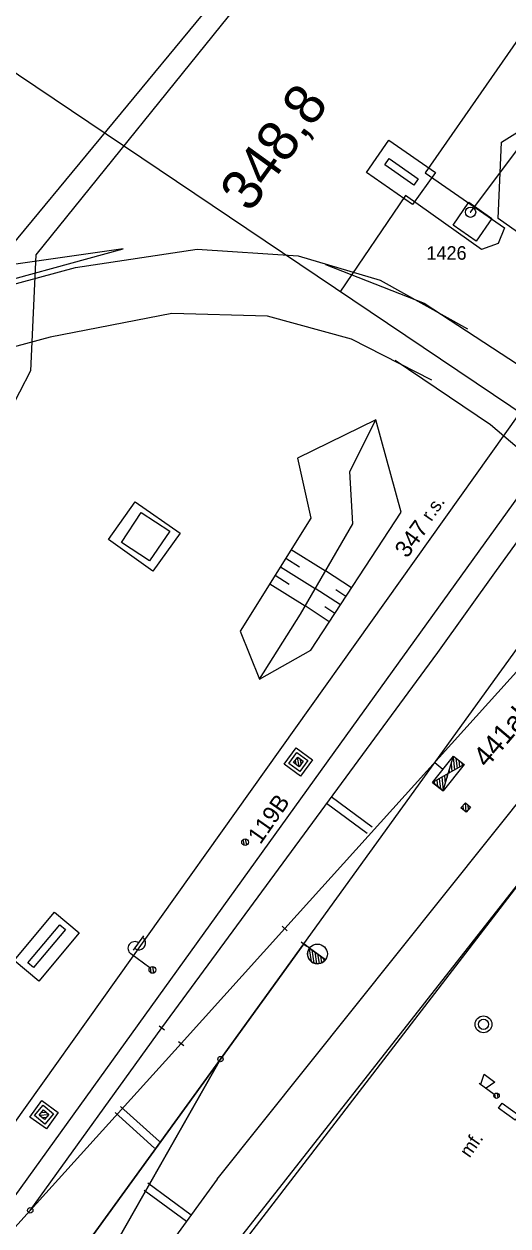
# Model space of a CAD drawing. Extents: x -469926 to -462499, y -1098642 to -1092733.
# Drawn here: x -465755.3 to -465719.5, y -1095836.3 to -1095747.3 of the extents above; entities that cross this region are included whole.
import ezdxf

# ---------------------------------------------------------------- set-up
doc = ezdxf.new("R2010")
doc.units = 0
for name, color, linetype in [('Vrstva 1', 7, 'Continuous'), ('Vrstva 11', 7, 'Continuous'), ('Vrstva 12', 7, 'Continuous'), ('Vrstva 13', 7, 'Continuous'), ('Vrstva 16', 7, 'Continuous'), ('Vrstva 2', 7, 'Continuous'), ('Vrstva 46', 7, 'Continuous'), ('Vrstva 48', 7, 'Continuous'), ('Vrstva 50', 7, 'Continuous'), ('Vrstva 51', 7, 'Continuous'), ('Vrstva 55', 7, 'Continuous'), ('Vrstva 58', 7, 'Continuous'), ('Vrstva 62', 7, 'Continuous'), ('Vrstva 7', 7, 'Continuous')]:
    doc.layers.add(name, color=color, linetype=linetype)

msp = doc.modelspace()

# ---------------------------------------------------------------- linework, layer by layer
at = {"layer": 'Vrstva 1'}
for p, q in [((-465788.8, -1095874.65), (-465635.97, -1095660.09)), ((-465720.35, -1095787.76), (-465712.45, -1095776.88)), ((-465734.607, -1095815.42), (-465712.071, -1095784.2)), ((-465736.023, -1095814.275), (-465710.284, -1095785.74)), ((-465741.022, -1095832.841), (-465709.466, -1095793.302)), ((-465754.17, -1095857.1), (-465718.76, -1095811.1)), ((-465750.523, -1095837.402), (-465740.776, -1095823.941))]:
    msp.add_line(p, q, dxfattribs=at)
for points in [[(-465745.127, -1095821.621), (-465724.675, -1095793.843), (-465720.35, -1095787.76)], [(-465736.023, -1095814.275), (-465743.694, -1095822.788)], [(-465734.607, -1095815.42), (-465740.776, -1095823.941), (-465750.523, -1095837.402)], [(-465775.781, -1095858.01), (-465766.01, -1095847.458), (-465754.867, -1095835.14), (-465745.127, -1095821.621)], [(-465766.01, -1095847.458), (-465754.867, -1095835.14), (-465743.694, -1095822.788)], [(-465754.867, -1095835.14), (-465743.694, -1095822.788)], [(-465741.022, -1095832.841), (-465753.551, -1095850.09), (-465764.044, -1095864.57)]]:
    msp.add_lwpolyline(points, dxfattribs=at)
at = {"layer": 'Vrstva 12'}
for p, q in [((-465735.172, -1095802.135), (-465735.221, -1095801.808)), ((-465734.959, -1095802.293), (-465735.063, -1095801.595)), ((-465734.801, -1095802.082), (-465734.85, -1095801.751)), ((-465722.598, -1095805.672), (-465722.64, -1095804.968)), ((-465722.796, -1095805.496), (-465722.816, -1095805.166)), ((-465722.422, -1095805.476), (-465722.441, -1095805.142)), ((-465754.192, -1095828.09), (-465753.489, -1095828.032)), ((-465754.021, -1095827.887), (-465753.691, -1095827.86)), ((-465753.993, -1095828.261), (-465753.659, -1095828.234))]:
    msp.add_line(p, q, dxfattribs=at)
for points in [[(-465735.169, -1095800.895), (-465733.961, -1095801.785), (-465734.851, -1095802.993), (-465736.059, -1095802.103)], [(-465735.71, -1095802.047), (-465735.113, -1095801.244), (-465734.31, -1095801.841), (-465734.907, -1095802.644)], [(-465735.36, -1095801.996), (-465735.062, -1095801.594), (-465734.66, -1095801.892), (-465734.958, -1095802.294)], [(-465722.971, -1095805.341), (-465722.639, -1095804.967), (-465722.265, -1095805.299), (-465722.597, -1095805.673)], [(-465754.011, -1095827.015), (-465752.794, -1095827.892), (-465753.671, -1095829.109), (-465754.888, -1095828.232)], [(-465753.898, -1095827.356), (-465753.135, -1095828.005), (-465753.784, -1095828.768), (-465754.547, -1095828.119)], [(-465753.87, -1095827.709), (-465753.488, -1095828.033), (-465753.812, -1095828.414), (-465754.193, -1095828.091)]]:
    msp.add_lwpolyline(points, close=True, dxfattribs=at)
for points in [[(-465735.36, -1095801.996), (-465735.062, -1095801.594), (-465734.66, -1095801.892), (-465734.958, -1095802.294), (-465735.36, -1095801.996)], [(-465722.971, -1095805.341), (-465722.639, -1095804.967), (-465722.265, -1095805.299), (-465722.597, -1095805.673), (-465722.971, -1095805.341)], [(-465753.87, -1095827.709), (-465753.488, -1095828.033), (-465753.812, -1095828.414), (-465754.193, -1095828.091), (-465753.87, -1095827.709)]]:
    msp.add_lwpolyline(points, dxfattribs=at)
at = {"layer": 'Vrstva 13'}
for p, q in [((-465733.01, -1095765.12), (-465725.7, -1095767.97)), ((-465725.7, -1095767.97), (-465717.46, -1095773.38)), ((-465727.85, -1095772.21), (-465720.79, -1095776.97)), ((-465720.79, -1095776.97), (-465716.442, -1095780.676))]:
    msp.add_line(p, q, dxfattribs=at)
for points in [[(-465838.428, -1095771.566), (-465834.57, -1095778.174), (-465829.935, -1095781.442), (-465824.938, -1095782.605), (-465818.606, -1095782.506), (-465808.495, -1095780.589), (-465777.214, -1095772.3), (-465751.524, -1095765.336), (-465742.5, -1095763.978), (-465735.021, -1095764.484), (-465728.964, -1095766.278), (-465722.487, -1095769.872)], [(-465725.124, -1095773.69), (-465731.083, -1095770.643), (-465737.306, -1095768.943), (-465744.388, -1095768.752), (-465753.392, -1095770.491), (-465774.436, -1095776.17), (-465804.42, -1095784.289), (-465857.81, -1095799.241), (-465876.937, -1095806.252), (-465888.375, -1095812.085), (-465898.457, -1095818.323), (-465902.347, -1095822), (-465903.923, -1095826.471), (-465903.648, -1095830.838), (-465902.613, -1095834.901), (-465899.413, -1095840.431), (-465874.372, -1095879.591), (-465865.495, -1095894.209)]]:
    msp.add_lwpolyline(points, dxfattribs=at)
at = {"layer": 'Vrstva 16'}
for p, q in [((-465722.26, -1095761.25), (-465583.59, -1095575.87)), ((-465722.285, -1095761.25), (-465722.235, -1095761.25))]:
    msp.add_line(p, q, dxfattribs=at)
msp.add_circle((-465722.26, -1095761.25), 0.378, dxfattribs=at)
at = {"layer": 'Vrstva 2'}
for p, q in [((-465724.306, -1095802.495), (-465724.895, -1095802.021)), ((-465723.699, -1095802.093), (-465723.637, -1095802.647)), ((-465723.552, -1095801.606), (-465723.447, -1095802.539)), ((-465723.345, -1095801.658), (-465723.258, -1095802.432)), ((-465723.124, -1095801.834), (-465723.069, -1095802.324)), ((-465722.903, -1095802.01), (-465722.88, -1095802.217)), ((-465724.77, -1095803.292), (-465724.718, -1095803.761)), ((-465724.581, -1095803.184), (-465724.496, -1095803.938)), ((-465724.392, -1095803.076), (-465724.284, -1095804.035)), ((-465724.203, -1095802.969), (-465724.137, -1095803.549)), ((-465724.014, -1095802.861), (-465723.991, -1095803.063)), ((-465723.845, -1095802.579), (-465723.826, -1095802.754)), ((-465724.96, -1095803.399), (-465724.939, -1095803.585))]:
    msp.add_line(p, q, dxfattribs=at)
msp.add_lwpolyline([(-465722.743, -1095802.139), (-465724.302, -1095804.093), (-465725.084, -1095803.47), (-465723.525, -1095801.515)], close=True, dxfattribs=at)
for points in [[(-465722.743, -1095802.139), (-465723.913, -1095802.804), (-465723.525, -1095801.515), (-465722.743, -1095802.139)], [(-465724.302, -1095804.093), (-465723.913, -1095802.804), (-465725.084, -1095803.47), (-465724.302, -1095804.093)]]:
    msp.add_lwpolyline(points, dxfattribs=at)
at = {"layer": 'Vrstva 46'}
msp.add_lwpolyline([(-465739.37, -1095837.25), (-465718.79, -1095811.03), (-465716.12, -1095812.96), (-465704.25, -1095819.84)], dxfattribs=at)
at = {"layer": 'Vrstva 48'}
for points in [[(-465735.544, -1095786.219), (-465733, -1095787.804)], [(-465735.941, -1095786.856), (-465734.916, -1095787.494)], [(-465736.734, -1095788.129), (-465735.694, -1095788.777)], [(-465736.337, -1095787.492), (-465733.756, -1095789.101)], [(-465731.077, -1095789.063), (-465732.999, -1095787.802)], [(-465737.131, -1095788.765), (-465734.513, -1095790.397)], [(-465731.899, -1095790.317), (-465733.756, -1095789.099)], [(-465731.488, -1095789.69), (-465732.244, -1095789.194)], [(-465732.722, -1095791.571), (-465734.513, -1095790.397)], [(-465732.31, -1095790.944), (-465733.04, -1095790.466)]]:
    msp.add_lwpolyline(points, dxfattribs=at)
at = {"layer": 'Vrstva 50'}
msp.add_line((-465757.57, -1095765.332), (-465684.425, -1095676.798), dxfattribs=at)
at = {"layer": 'Vrstva 51'}
for p, q in [((-465684.073, -1095677.119), (-465754.445, -1095764.415)), ((-465754.445, -1095764.415), (-465754.852, -1095772.991)), ((-465754.852, -1095772.991), (-465783.762, -1095828.944))]:
    msp.add_line(p, q, dxfattribs=at)
at = {"layer": 'Vrstva 55'}
for p, q in [((-465722.26, -1095761.25), (-465583.59, -1095575.87)), ((-465722.285, -1095761.25), (-465722.235, -1095761.25)), ((-465731.045, -1095806.019), (-465731.045, -1095806.019)), ((-465739.009, -1095808.128), (-465739.099, -1095807.68)), ((-465738.824, -1095808.094), (-465738.916, -1095807.64)), ((-465747.216, -1095815.867), (-465746.442, -1095814.822)), ((-465736.213, -1095814.112), (-465735.833, -1095814.438)), ((-465736.023, -1095814.275), (-465736.023, -1095814.275)), ((-465740.776, -1095823.941), (-465734.607, -1095815.42)), ((-465734.804, -1095815.265), (-465734.41, -1095815.575)), ((-465734.607, -1095815.42), (-465734.607, -1095815.42)), ((-465734.19, -1095815.722), (-465734.607, -1095815.42)), ((-465734.191, -1095815.723), (-465734.19, -1095815.722)), ((-465733.008, -1095816.585), (-465734.191, -1095815.723)), ((-465734.19, -1095815.722), (-465733.008, -1095816.585)), ((-465746.018, -1095817.19), (-465747.424, -1095816.148)), ((-465734.22, -1095815.77), (-465734.074, -1095816.709)), ((-465734.019, -1095815.848), (-465733.864, -1095816.835)), ((-465733.804, -1095816.004), (-465733.667, -1095816.881)), ((-465733.591, -1095816.161), (-465733.479, -1095816.874)), ((-465733.376, -1095816.317), (-465733.298, -1095816.819)), ((-465733.162, -1095816.473), (-465733.125, -1095816.709)), ((-465745.901, -1095817.575), (-465745.966, -1095817.139)), ((-465745.712, -1095817.565), (-465745.783, -1095817.091)), ((-465754.867, -1095835.14), (-465745.127, -1095821.621)), ((-465745.329, -1095821.473), (-465744.925, -1095821.769)), ((-465745.127, -1095821.621), (-465745.127, -1095821.621)), ((-465743.896, -1095822.639), (-465743.492, -1095822.937)), ((-465743.694, -1095822.788), (-465743.694, -1095822.788)), ((-465740.776, -1095823.941), (-465748.993, -1095838.414)), ((-465721.51, -1095825.801), (-465721.264, -1095825.05)), ((-465721.264, -1095825.05), (-465720.461, -1095825.647)), ((-465721.631, -1095825.712), (-465720.507, -1095826.544)), ((-465720.461, -1095825.647), (-465721.109, -1095826.1)), ((-465720.41, -1095826.842), (-465720.461, -1095826.497)), ((-465720.212, -1095826.809), (-465720.262, -1095826.471)), ((-465746.882, -1095829.036), (-465746.882, -1095829.036)), ((-465744.497, -1095834.692), (-465744.497, -1095834.692))]:
    msp.add_line(p, q, dxfattribs=at)
for points in [[(-465609.888, -1095625.282), (-465638.963, -1095671.505), (-465681.941, -1095731.193), (-465731.933, -1095800.622), (-465757.477, -1095836.099), (-465808.227, -1095887.932), (-465849.014, -1095921.297)], [(-465777.86, -1095736.176), (-465714.07, -1095779.117)], [(-465707.358, -1095756.532), (-465711.944, -1095759.891), (-465717.519, -1095763.613), (-465720.23, -1095761.71), (-465719.982, -1095756.053), (-465713.877, -1095752.269)], [(-465729.964, -1095758.307), (-465728.301, -1095755.91), (-465724.854, -1095758.302), (-465726.562, -1095760.668), (-465729.964, -1095758.307)], [(-465728.612, -1095757.735), (-465728.297, -1095757.284), (-465726.144, -1095758.788), (-465726.459, -1095759.239), (-465728.612, -1095757.735)], [(-465723.562, -1095762.202), (-465722.382, -1095760.501), (-465720.683, -1095761.703), (-465721.853, -1095763.388), (-465723.562, -1095762.202)], [(-465838.428, -1095771.566), (-465834.57, -1095778.174), (-465829.935, -1095781.442), (-465824.938, -1095782.605), (-465818.606, -1095782.506), (-465808.495, -1095780.589), (-465777.214, -1095772.3), (-465751.524, -1095765.336), (-465742.5, -1095763.978), (-465735.021, -1095764.484), (-465728.964, -1095766.278), (-465722.487, -1095769.872)], [(-465785.648, -1095773.98), (-465759.87, -1095767.225), (-465747.992, -1095763.955), (-465767.148, -1095766.706), (-465788.561, -1095771.396)], [(-465737.882, -1095795.826), (-465734.099, -1095793.672), (-465727.404, -1095783.462), (-465729.286, -1095776.626), (-465735.077, -1095779.458), (-465734.095, -1095783.893), (-465739.313, -1095792.266), (-465737.882, -1095795.826)], [(-465737.882, -1095795.826), (-465734.865, -1095791), (-465730.967, -1095784.318), (-465731.189, -1095780.453), (-465729.286, -1095776.626)], [(-465749.069, -1095785.489), (-465747.084, -1095782.679), (-465743.773, -1095785.017), (-465745.777, -1095787.813), (-465749.069, -1095785.489)], [(-465748.108, -1095785.697), (-465746.641, -1095783.466), (-465744.527, -1095784.856), (-465746.034, -1095787.059), (-465748.108, -1095785.697)], [(-465732.937, -1095804.991), (-465729.923, -1095807.216)], [(-465732.58, -1095804.509), (-465729.537, -1095806.742)], [(-465756.048, -1095816.638), (-465753.075, -1095813.072), (-465751.241, -1095814.595), (-465754.217, -1095818.165), (-465756.048, -1095816.638)], [(-465755.035, -1095816.809), (-465752.673, -1095814.002), (-465752.252, -1095814.356), (-465754.614, -1095817.163), (-465755.035, -1095816.809)], [(-465748.993, -1095838.414), (-465740.776, -1095823.941)], [(-465720.198, -1095827.585), (-465719.932, -1095827.21), (-465718.698, -1095828.092), (-465718.956, -1095828.469), (-465720.198, -1095827.585)], [(-465745.661, -1095830.54), (-465748.576, -1095827.907)], [(-465745.305, -1095830.051), (-465748.173, -1095827.462)], [(-465746.147, -1095833.111), (-465742.944, -1095835.459)], [(-465746.438, -1095833.637), (-465743.299, -1095835.943)]]:
    msp.add_lwpolyline(points, dxfattribs=at)
for centre, radius in [((-465722.26, -1095761.25), 0.378), ((-465738.958, -1095807.885), 0.25), ((-465733.597, -1095816.157), 0.731), ((-465745.817, -1095817.339), 0.25), ((-465745.817, -1095817.339), 0.25), ((-465721.301, -1095821.368), 0.623), ((-465721.301, -1095821.368), 0.376), ((-465740.776, -1095823.941), 0.2), ((-465720.34, -1095826.655), 0.201), ((-465720.34, -1095826.655), 0.2), ((-465754.867, -1095835.14), 0.2)]:
    msp.add_circle(centre, radius, dxfattribs=at)
for centre, radius, start, end in [((-465747.126, -1095815.746), 0.5, 53.45662, 233.45662), ((-465746.823, -1095815.348), 0.5, 232.75405, 54.15919), ((-465733.6, -1095816.154), 0.732, 143.90059, 323.86144)]:
    msp.add_arc(centre, radius, start, end, dxfattribs=at)
at = {"layer": 'Vrstva 58'}
for points in [[(-465691.234, -1095708.918), (-465725.631, -1095758.328)], [(-465725.631, -1095758.328), (-465719.746, -1095762.401), (-465720.206, -1095763.559), (-465721.447, -1095764.009), (-465727.067, -1095760.015)], [(-465727.067, -1095760.015), (-465731.936, -1095767.169)]]:
    msp.add_lwpolyline(points, dxfattribs=at)
at = {"layer": 'Vrstva 62'}
msp.add_lwpolyline([(-465785.648, -1095773.98), (-465759.87, -1095767.225), (-465747.992, -1095763.955), (-465767.148, -1095766.706), (-465788.561, -1095771.396)], dxfattribs=at)

# ---------------------------------------------------------------- texts
at = {"layer": 'Vrstva 11'}
msp.add_text('119B', height=1.25, rotation=55.1125, dxfattribs=at).set_placement((-465737.827, -1095808.106))
at = {"layer": 'Vrstva 2'}
msp.add_text('441ab', height=1.5, rotation=49.75348, dxfattribs=at).set_placement((-465721.054, -1095802.441))
at = {"layer": 'Vrstva 55'}
msp.add_text('1426', height=1, dxfattribs=at).set_placement((-465725.531, -1095764.764))
for s, rotation, p in [('r.s.', 55.54375, (-465725.162, -1095784.192)), ('mf.', 55.11811, (-465722.335, -1095831.308))]:
    msp.add_text(s, height=1, rotation=rotation, dxfattribs=at).set_placement(p)
at = {"layer": 'Vrstva 7'}
for s, height, rotation, p in [('348,8', 3, 54.08828, (-465738.587, -1095761.353)), ('347', 1.25, 54.01649, (-465726.961, -1095786.915))]:
    msp.add_text(s, height=height, rotation=rotation, dxfattribs=at).set_placement(p)

doc.saveas('drawing.dxf')
